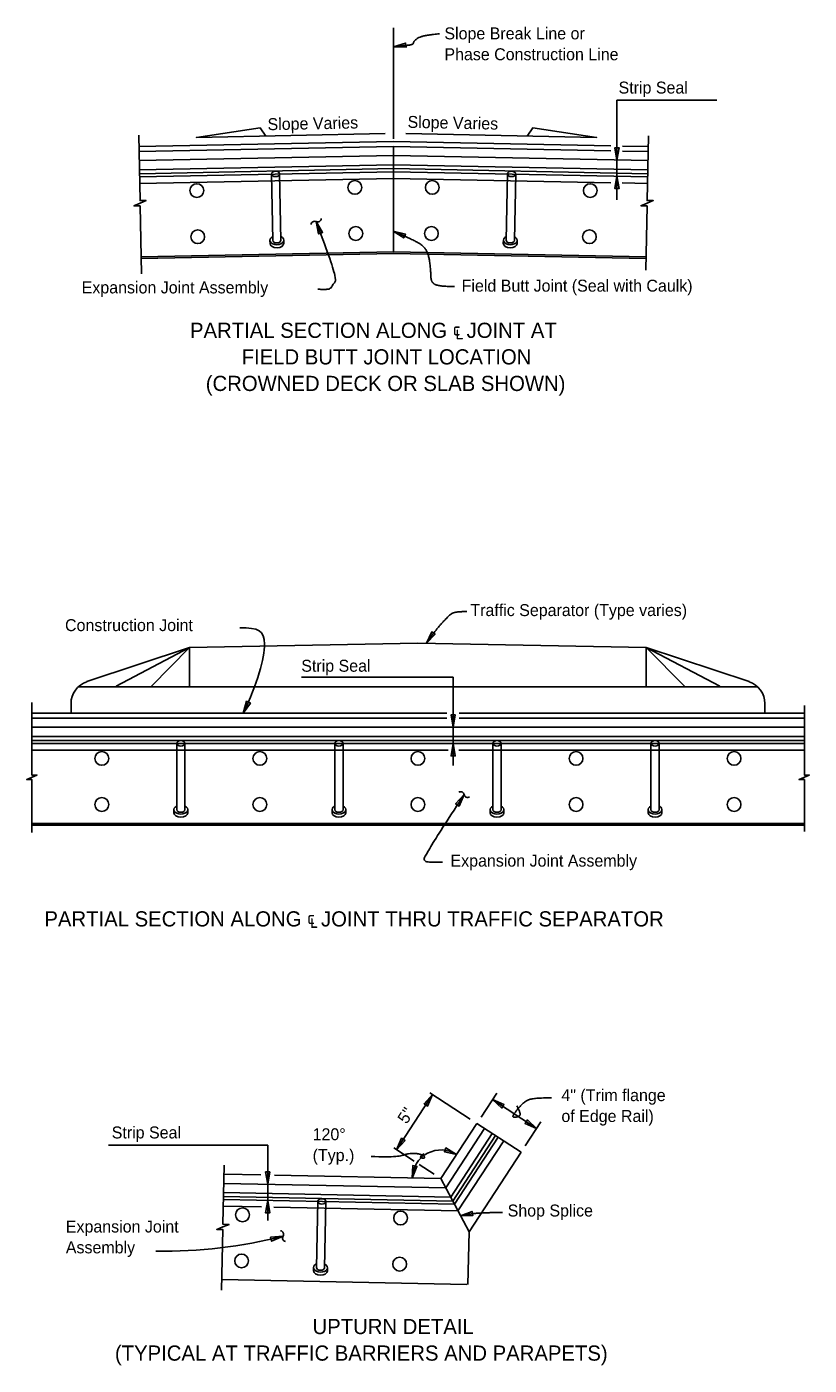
# Model space of a CAD drawing. Extents: x 0 to 15.3, y 0 to 9.9.
# Drawn here: x 10.31 to 15.26, y 0.65 to 9.11 of the extents above; entities that cross this region are included whole.
import ezdxf

# ---------------------------------------------------------------- set-up
doc = ezdxf.new("R2010")
doc.units = 0
for name, color, linetype in [('Dimension', 7, 'Continuous'), ('Miscellaneous', 7, 'Continuous'), ('SteelGirder', 7, 'Continuous'), ('SteelGirder_h', 7, 'Continuous'), ('SupstrConc', 7, 'Continuous'), ('TextStructures', 7, 'Continuous')]:
    doc.layers.add(name, color=color, linetype=linetype)

msp = doc.modelspace()

# ---------------------------------------------------------------- linework, layer by layer
at = {"layer": 'Dimension'}
for p, q in [((12.6349, 8.405), (12.6349, 9.1063)), ((14.048, 8.6486), (14.6798, 8.6486)), ((14.048, 8.2701), (14.048, 8.6486)), ((14.048, 8.1672), (14.048, 8.2701)), ((14.048, 8.0185), (14.048, 8.1672)), ((12.6541, 2.0092), (12.882, 2.3581)), ((12.8646, 2.3694), (13.1199, 2.2027)), ((13.1884, 2.2152), (13.2874, 2.3668)), ((13.2608, 2.3261), (13.5399, 2.1439)), ((13.4675, 2.033), (13.5665, 2.1846)), ((11.8388, 2.0386), (10.8315, 2.0386)), ((11.8388, 1.7904), (11.8388, 2.0386)), ((12.6367, 2.0205), (12.7644, 1.9372)), ((12.7975, 1.9156), (12.892, 1.8538)), ((11.8388, 1.6875), (11.8388, 1.7904)), ((11.8388, 1.5616), (11.8388, 1.6875))]:
    msp.add_line(p, q, dxfattribs=at)
for points in [[(12.6348, 8.9871), (12.7139, 8.9832), (12.7107, 9.0095)], [(14.048, 8.2701), (14.0612, 8.3482), (14.0347, 8.3482)], [(14.048, 8.1672), (14.0348, 8.0891), (14.0612, 8.0891)], [(12.1455, 7.8806), (12.1607, 7.8028), (12.1854, 7.8122)], [(12.6324, 7.8192), (12.6998, 7.7776), (12.7097, 7.8021)], [(12.8424, 5.2135), (12.898, 5.2699), (12.8763, 5.285)], [(11.6831, 4.7701), (11.7291, 4.8345), (11.7053, 4.8461)], [(13.012, 4.6813), (13.0252, 4.7594), (12.9987, 4.7594)], [(13.012, 4.5783), (12.9987, 4.5002), (13.0252, 4.5002)], [(13.0814, 4.2556), (13.0275, 4.1976), (13.0497, 4.1831)], [(12.882, 2.3579), (12.8282, 2.2998), (12.8503, 2.2853)], [(13.2608, 2.326), (13.319, 2.2723), (13.3334, 2.2944)], [(13.5399, 2.1437), (13.4817, 2.1975), (13.4673, 2.1754)], [(12.6541, 2.0091), (12.7079, 2.0672), (12.6857, 2.0817)], [(13.0335, 1.978), (12.9665, 2.0201), (12.9563, 1.9957)], [(11.8388, 1.7904), (11.8521, 1.8685), (11.8256, 1.8685)], [(12.7529, 1.8297), (12.7823, 1.9032), (12.7564, 1.9088)], [(11.8388, 1.6874), (11.8256, 1.6093), (11.8521, 1.6093)], [(13.0577, 1.5909), (13.1369, 1.5932), (13.1317, 1.6191)], [(11.9359, 1.4624), (11.857, 1.4556), (11.8637, 1.4299)]]:
    msp.add_lwpolyline(points, close=True, dxfattribs=at)
for points in [[(11.8273, 8.4211), (11.7907, 8.4735), (11.3873, 8.4136), (12.581, 8.4375)], [(13.4792, 8.4204), (13.5158, 8.4728), (13.9192, 8.4129), (12.7123, 8.437)], [(11.0402, 7.5508), (11.0316, 7.9801), (10.9928, 7.9793), (11.0312, 7.997), (11.0697, 8.0146), (11.0309, 8.0138), (11.0226, 8.4281)], [(14.23, 7.5731), (14.2382, 7.9801), (14.1995, 7.9808), (14.2386, 7.997), (14.2776, 8.0131), (14.2389, 8.0138), (14.2471, 8.4241)], [(13.0119, 4.6812), (13.0119, 4.9981), (12.0516, 4.9981)], [(10.3476, 4.0158), (10.3476, 4.3509), (10.3146, 4.3509), (10.3785, 4.3792), (10.3476, 4.3792), (10.3476, 4.8376)], [(15.2336, 4.0212), (15.2336, 4.3509), (15.2005, 4.3509), (15.2645, 4.3792), (15.2336, 4.3792), (15.2336, 4.8188)], [(13.0119, 4.5784), (13.0119, 4.6812)], [(13.0119, 4.4403), (13.0119, 4.5784)], [(11.5473, 1.1208), (11.555, 1.5035), (11.5163, 1.5042), (11.5553, 1.5204), (11.5944, 1.5365), (11.5557, 1.5372), (11.5632, 1.9102)]]:
    msp.add_lwpolyline(points, dxfattribs=at)
for centre, radius, start, end in [((12.1357, 7.8602), 0.0224, 64.86266, 176.58988), ((12.1547, 7.9007), 0.0224, 244.86266, 356.58988), ((13.0592, 4.2515), 0.0224, 10.95797, 122.68519), ((13.1031, 4.26), 0.0224, 190.95797, 302.68519), ((12.9343, 1.8262), 0.1814, 56.85433, 178.85433), ((11.1935, 4.3202), 2.9527, 268.80522, 284.56288), ((11.9167, 1.4743), 0.0224, 328.74218, 80.4694), ((11.9549, 1.4511), 0.0224, 148.74218, 260.4694)]:
    msp.add_arc(centre, radius, start, end, dxfattribs=at)
for points, degree in [([(12.9245, 9.0692), (12.8128, 9.0585), (12.7614, 9.0225), (12.7598, 8.9988), (12.6843, 8.9929), (12.6349, 8.9869)], 2), ([(12.156, 7.4527), (12.2005, 7.4507), (12.2368, 7.4548), (12.253, 7.4871), (12.2822, 7.5184), (12.1455, 7.8806)], 2), ([(13.021, 7.4699), (12.9189, 7.4699), (12.8706, 7.4986), (12.8706, 7.5774), (12.8509, 7.7028), (12.7739, 7.7619), (12.6325, 7.8192)], 2), ([(13.0988, 5.4135), (13.0276, 5.4135), (12.9874, 5.3921), (12.8988, 5.294), (12.8424, 5.2134)], 2), ([(11.6623, 5.3112), (11.7778, 5.3112), (11.8614, 5.2798), (11.7744, 4.9579), (11.6831, 4.7701)], 3), ([(12.9445, 3.8285), (12.9028, 3.8285), (12.829, 3.8285), (12.829, 3.8702), (13.0814, 4.2556)], 2), ([(13.633, 2.3369), (13.5434, 2.3369), (13.4687, 2.322), (13.4119, 2.2562), (13.3821, 2.2144), (13.4179, 2.2144), (13.4448, 2.2323), (13.4149, 2.2861)], 2), ([(12.4933, 1.9656), (12.6532, 1.9604), (12.7234, 1.9843), (12.7779, 1.9865), (12.8272, 1.9738), (12.8317, 1.9559), (12.822, 1.9544), (12.7973, 1.9611), (12.8257, 1.9843)], 2), ([(13.3249, 1.6127), (13.2322, 1.6108), (13.1308, 1.6055), (13.0577, 1.5909)], 2)]:
    msp.add_open_spline(points, degree=degree, dxfattribs=at)
at = {"layer": 'Miscellaneous'}
msp.add_line((13.7694, 8.2735), (13.7698, 8.2742), dxfattribs=at)
for points in [[(12.6349, 8.2983), (11.0253, 8.2662)], [(12.6349, 8.2983), (14.2446, 8.2662)], [(12.6366, 8.2159), (11.0269, 8.1837)], [(12.6349, 8.2158), (14.2429, 8.1837)], [(12.637, 8.1955), (11.0273, 8.1633)], [(12.6349, 8.1954), (14.2425, 8.1633)], [(15.2336, 4.6812), (10.3476, 4.6812)], [(15.2336, 4.5987), (10.3476, 4.5987)], [(15.2336, 4.5783), (10.3476, 4.5784)], [(13.2105, 2.1435), (12.9652, 1.7679)], [(13.2796, 2.0984), (13.0092, 1.6845)], [(13.2966, 2.0873), (13.0201, 1.6639)], [(11.5609, 1.7959), (12.9652, 1.7679)], [(11.5592, 1.7135), (13.0092, 1.6845)], [(11.5588, 1.6931), (13.0201, 1.6639)]]:
    msp.add_lwpolyline(points, dxfattribs=at)
at = {"layer": 'SteelGirder'}
for p, q in [((12.6349, 8.356), (12.6349, 8.2983)), ((12.6349, 8.1954), (12.6349, 7.6892)), ((13.1622, 2.1751), (13.4413, 1.9928)), ((13.1124, 1.4892), (12.9343, 1.8262)), ((13.1057, 1.1559), (13.1124, 1.4892))]:
    msp.add_line(p, q, dxfattribs=at)
for points in [[(12.6349, 8.356), (11.0241, 8.3238)], [(12.6349, 8.356), (14.009, 8.3286)], [(14.0835, 8.3271), (14.2457, 8.3238)], [(12.6349, 7.6892), (11.0374, 7.6573)], [(12.6349, 7.6892), (14.2324, 7.6573)], [(12.9716, 4.7389), (10.3476, 4.7389)], [(15.2336, 4.7389), (13.0498, 4.7389)], [(15.2336, 4.0722), (10.3476, 4.0722)], [(13.1622, 2.1751), (12.9343, 1.8262)], [(13.4413, 1.9928), (13.1124, 1.4892)], [(11.562, 1.8536), (11.7946, 1.849)], [(11.8809, 1.8472), (12.9343, 1.8262)], [(11.5487, 1.187), (13.0978, 1.1561)]]:
    msp.add_lwpolyline(points, dxfattribs=at)
at = {"layer": 'SteelGirder_h'}
for p, q in [((12.6349, 8.2983), (12.6349, 8.1954)), ((11.8706, 7.7623), (11.8622, 8.1814)), ((11.9227, 7.7633), (11.9143, 8.1825)), ((13.3472, 7.7633), (13.3556, 8.1825)), ((13.3993, 7.7623), (13.4076, 8.1814)), ((11.8534, 7.7422), (11.8531, 7.7619)), ((11.9402, 7.7637), (11.9406, 7.7439)), ((13.3292, 7.7439), (13.3296, 7.7637)), ((13.4168, 7.7619), (13.4164, 7.7422)), ((11.2631, 4.1605), (11.2631, 4.5798)), ((11.3152, 4.1605), (11.3152, 4.5798)), ((12.2631, 4.1605), (12.2631, 4.5798)), ((12.3152, 4.1605), (12.3152, 4.5798)), ((13.2631, 4.1605), (13.2631, 4.5798)), ((13.3152, 4.1605), (13.3152, 4.5798)), ((14.2631, 4.1605), (14.2631, 4.5798)), ((14.3152, 4.1605), (14.3152, 4.5798)), ((11.2456, 4.1408), (11.2456, 4.1605)), ((11.3328, 4.1605), (11.3328, 4.1408)), ((12.2456, 4.1408), (12.2456, 4.1605)), ((12.3328, 4.1605), (12.3328, 4.1408)), ((13.2456, 4.1408), (13.2456, 4.1605)), ((13.3328, 4.1605), (13.3328, 4.1408)), ((14.2456, 4.1408), (14.2456, 4.1605)), ((14.3328, 4.1605), (14.3328, 4.1408)), ((12.1469, 1.2634), (12.1553, 1.6826)), ((12.199, 1.2624), (12.2074, 1.6816)), ((12.1289, 1.2441), (12.1293, 1.2638)), ((12.2165, 1.262), (12.2161, 1.2423))]:
    msp.add_line(p, q, dxfattribs=at)
for points in [[(12.6349, 8.24), (11.0264, 8.2079)], [(12.6349, 8.24), (14.2434, 8.2079)], [(12.6349, 8.1537), (11.0282, 8.1216)], [(12.6349, 8.1537), (14.0095, 8.1262)], [(14.0801, 8.1248), (14.2417, 8.1216)], [(15.2336, 4.6229), (10.3476, 4.6229)], [(12.9812, 4.5367), (10.3476, 4.5367)], [(15.2336, 4.5366), (13.0471, 4.5367)], [(13.2593, 2.1116), (12.9963, 1.7089)], [(13.3315, 2.0645), (13.0424, 1.6217)], [(11.5597, 1.7377), (12.9963, 1.7089)], [(11.558, 1.6514), (11.7987, 1.6466)], [(11.8768, 1.645), (13.0424, 1.6217)]]:
    msp.add_lwpolyline(points, dxfattribs=at)
for centre in [(12.3901, 8.0967), (12.8798, 8.0967), (11.3903, 8.0767), (13.8796, 8.0767), (11.3961, 7.7851), (12.3959, 7.8051), (12.874, 7.8051), (13.8738, 7.7851), (10.7892, 4.4845), (11.7892, 4.4845), (12.7892, 4.4845), (13.7892, 4.4845), (14.7892, 4.4845), (10.7892, 4.1928), (11.7892, 4.1928), (12.7892, 4.1928), (13.7892, 4.1928), (14.7892, 4.1928), (11.6795, 1.5968), (12.6793, 1.5769), (11.6737, 1.3052), (12.6735, 1.2852)]:
    msp.add_circle(centre, 0.0436, dxfattribs=at)
for centre, major_axis in [((11.8883, 8.182), (0.026, 0.0005)), ((13.3816, 8.182), (0.026, -0.0005)), ((11.2892, 4.5798), (0.0261, 0)), ((12.2892, 4.5798), (0.0261, 0)), ((13.2892, 4.5798), (0.0261, 0)), ((14.2892, 4.5798), (0.0261, 0)), ((12.1813, 1.6821), (0.026, -0.0005))]:
    msp.add_ellipse(centre, major_axis=major_axis, ratio=0.654774, dxfattribs=at)
for centre, major_axis, ratio, start_param, end_param in [((11.8966, 7.7628), (0.0436, 0.0009), 0.654766, 2.211147, 7.21363), ((11.897, 7.7431), (0.0436, 0.0009), 0.654766, 3.141593, 6.283185), ((11.8966, 7.7628), (0.026, 0.0005), 0.654774, 3.1416, 6.283178), ((13.3732, 7.7628), (0.0436, -0.0009), 0.654766, 2.211147, 7.21363), ((13.3728, 7.7431), (0.0436, -0.0009), 0.654766, 3.141593, 6.283185), ((13.3732, 7.7628), (0.026, -0.0005), 0.654774, 3.1416, 6.283178), ((11.2892, 4.1605), (0.0436, 0), 0.654766, 2.211147, 7.21363), ((11.2892, 4.1605), (0.0261, 0), 0.654774, 3.1416, 6.283178), ((12.2892, 4.1605), (0.0436, 0), 0.654766, 2.211147, 7.21363), ((12.2892, 4.1605), (0.0261, 0), 0.654774, 3.1416, 6.283178), ((13.2892, 4.1605), (0.0436, 0), 0.654766, 2.211147, 7.21363), ((13.2892, 4.1605), (0.0261, 0), 0.654774, 3.1416, 6.283178), ((14.2892, 4.1605), (0.0436, 0), 0.654766, 2.211147, 7.21363), ((14.2892, 4.1605), (0.0261, 0), 0.654774, 3.1416, 6.283178), ((11.2892, 4.1408), (0.0436, 0), 0.654766, 3.141593, 6.283185), ((12.2892, 4.1408), (0.0436, 0), 0.654766, 3.141593, 6.283185), ((13.2892, 4.1408), (0.0436, 0), 0.654766, 3.141593, 6.283185), ((14.2892, 4.1408), (0.0436, 0), 0.654766, 3.141593, 6.283185), ((12.1729, 1.2629), (0.0436, -0.0009), 0.654766, 2.211147, 7.21363), ((12.1725, 1.2432), (0.0436, -0.0009), 0.654766, 3.141593, 6.283185), ((12.1729, 1.2629), (0.026, -0.0005), 0.654774, 3.1416, 6.283178)]:
    msp.add_ellipse(centre, major_axis=major_axis, ratio=ratio, start_param=start_param, end_param=end_param, dxfattribs=at)
at = {"layer": 'SupstrConc'}
for p, q in [((10.6942, 4.9701), (11.3445, 5.1868)), ((10.8797, 4.9411), (11.3445, 5.1868)), ((11.1013, 4.9397), (11.3445, 5.1868)), ((11.3445, 5.1868), (12.7892, 5.2136)), ((11.3445, 4.9369), (11.3445, 5.1868)), ((14.2338, 5.1868), (12.7892, 5.2136)), ((14.8841, 4.9701), (14.2338, 5.1868)), ((14.2338, 4.9369), (14.2338, 5.1868)), ((14.6986, 4.9411), (14.2338, 5.1868)), ((14.477, 4.9397), (14.2338, 5.1868)), ((10.6394, 4.9369), (14.9389, 4.9369)), ((10.5945, 4.7701), (10.5945, 4.8317)), ((14.9838, 4.7701), (14.9838, 4.8317)), ((10.3476, 4.0618), (15.2336, 4.0618))]:
    msp.add_line(p, q, dxfattribs=at)
for points in [[(12.6349, 8.3872), (11.0235, 8.355)], [(12.6349, 8.3872), (14.0096, 8.3598)], [(14.0842, 8.3583), (14.2464, 8.355)], [(12.6349, 7.6788), (11.0383, 7.6469)], [(12.6349, 7.6788), (14.2316, 7.6469)], [(12.9716, 4.7701), (10.3476, 4.7701)], [(15.2336, 4.7701), (13.0498, 4.7701)]]:
    msp.add_lwpolyline(points, dxfattribs=at)
for centre, start, end in [((10.7403, 4.8317), 108.43495, 180), ((14.838, 4.8317), 0, 71.56505)]:
    msp.add_arc(centre, 0.1458, start, end, dxfattribs=at)

# ---------------------------------------------------------------- texts
at = {"layer": 'TextStructures'}
for s, height, p in [('Slope Break Line or', 0.0756, (12.9566, 9.0335)), ('Phase Construction Line', 0.0756, (12.9566, 8.9015)), ('Strip Seal', 0.0756, (14.0583, 8.6907)), ('Expansion Joint Assembly', 0.0756, (10.662, 7.4263)), ('Field Butt Joint (Seal with Caulk)', 0.0756, (13.0657, 7.4374)), ('PARTIAL SECTION ALONG ℄ JOINT AT', 0.096, (11.3471, 7.1449)), ('FIELD BUTT JOINT LOCATION', 0.096, (11.6739, 6.9769)), ('(CROWNED DECK OR SLAB SHOWN)', 0.096, (11.4469, 6.8089)), ('Traffic Separator (Type varies)', 0.0756, (13.1209, 5.3849)), ('Construction Joint', 0.0756, (10.5566, 5.2897)), ('Strip Seal', 0.0756, (12.0511, 5.0329)), ('Expansion Joint Assembly', 0.0756, (12.9952, 3.8)), ('PARTIAL SECTION ALONG ℄ JOINT THRU TRAFFIC SEPARATOR', 0.096, (10.4261, 3.4213)), ('4" (Trim flange', 0.0756, (13.6967, 2.3163)), ('of Edge Rail)', 0.0756, (13.6967, 2.1843)), ('Strip Seal', 0.0756, (10.8519, 2.0803)), ('120° ', 0.0756, (12.123, 2.0689)), ('(Typ.)', 0.0756, (12.123, 1.9369)), ('Shop Splice', 0.0756, (13.3568, 1.5864)), ('Expansion Joint', 0.0756, (10.5617, 1.4852)), ('Assembly', 0.0756, (10.5617, 1.3532)), ('UPTURN DETAIL', 0.096, (12.1223, 0.8424)), ('(TYPICAL AT TRAFFIC BARRIERS AND PARAPETS)', 0.096, (10.8722, 0.6744))]:
    msp.add_text(s, height=height, dxfattribs=at).set_placement(p)
for s, rotation, p in [('Slope Varies', 1.14567, (11.8384, 8.4586)), ('Slope Varies', 358.85433, (12.7229, 8.4738)), ('5"', 56.85433, (12.7178, 2.1663))]:
    msp.add_text(s, height=0.0756, rotation=rotation, dxfattribs=at).set_placement(p)

doc.saveas('drawing.dxf')
